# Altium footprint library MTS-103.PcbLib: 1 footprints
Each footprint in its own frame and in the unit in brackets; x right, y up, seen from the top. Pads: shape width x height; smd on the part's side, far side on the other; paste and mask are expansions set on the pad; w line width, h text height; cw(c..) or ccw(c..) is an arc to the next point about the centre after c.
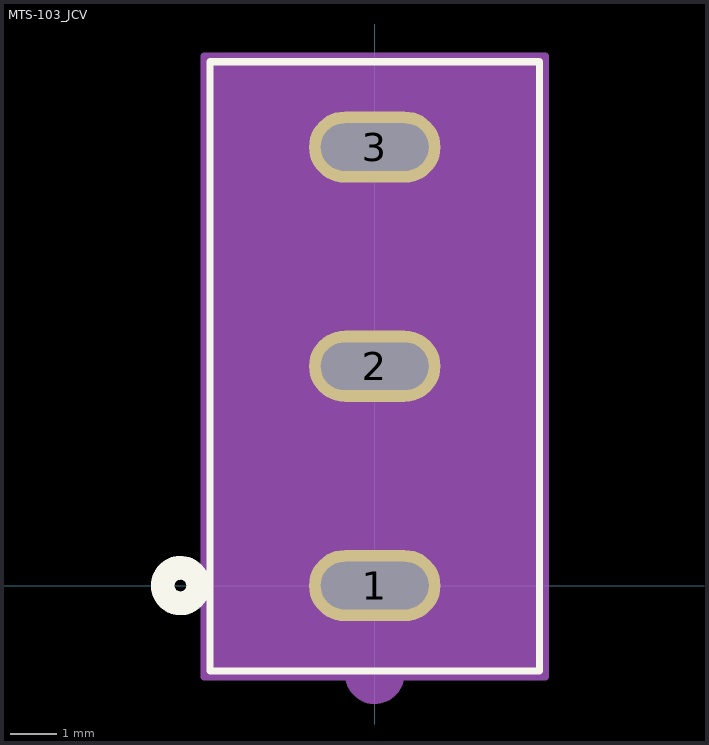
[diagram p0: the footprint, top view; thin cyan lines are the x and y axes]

## MTS-103_JCV [mil]
pads (3):
  oval 111x60 hole 40 slot 91 at 0 deg paste+0 mask+0: 1(0,0) 2(0,185.04) 3(0,370.08)
Top Overlay:
  circle w20: c-164,0 r15
  lines w6: -139,-71.96 139,-71.96 139,442.04 -139,442.04 -139,-71.96
  text ".Designator" at -137.5,160.04 h50
Bottom Overlay:
  circle w20: c-164,0 r15
Mechanical 13:
  circle w20: c0,-75 r15
  lines w1: -134,-66.96 134,-66.96 134,437.04 -134,437.04 -134,-66.96
  text ".Designator" at -137.5,160.04 h50
Mechanical 15:
  region: 144,447.04 -144,447.04 -144,-76.96 144,-76.96
  lines w6: -144,-76.96 -144,447.04 144,447.04 144,-76.96 -144,-76.96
